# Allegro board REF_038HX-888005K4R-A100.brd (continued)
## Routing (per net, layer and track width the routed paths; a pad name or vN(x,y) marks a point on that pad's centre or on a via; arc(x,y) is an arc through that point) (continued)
D11610: length 268.7
  TOP w0.203: v2(100.55,223.11) 100.84,222.81 107.29,222.81 109.67,220.43 SITE1.140
  L03_SIGNAL w0.135: 113.5,288.23 113.5,291.58 116.74,294.82 116.74,308.89 135.13,327.28 135.13,361.68 155.3,381.84 174.7,381.84 178.67,385.81 178.67,389.22
  L03_SIGNAL w0.145: 178.67,389.22 D116.10 ; 113.5,288.23 113.77,287.96 v2(114.23,287.96)
  L22_SIGNAL w0.135: 100.18,222.74 99.21,222.74 99.08,222.88 99.08,223.11 98.94,223.25 98.67,223.25 98.54,223.11 98.54,222.88 98.4,222.74 98.14,222.74 98,222.88 98,223.11 97.87,223.25 97.6,223.25 97.46,223.11 97.46,222.88 97.33,222.74 89.36,222.74 81.7,230.4 81.7,274.98 83.63,276.91 103.31,276.91 104.63,278.23 104.63,284.74 105.97,286.08 112.79,286.08 113.5,286.79 113.5,287.69
  L22_SIGNAL w0.145: 113.5,287.69 113.77,287.96 v2(114.23,287.96) ; 100.18,222.74 v2(100.55,223.11)
D11611: length 268.7
  TOP w0.203: v2(97.25,224.28) 97.55,224.57 107.72,224.57 111.06,221.23 SITE1.138
  L05_SIGNAL w0.135: 113.09,281.99 113.09,281.09 112.83,280.82 112.14,280.82 110.83,282.13 110.83,305.69 132.32,327.18 132.32,378.45 155.49,401.62 175.76,401.62 181.27,396.11 181.27,395.14
  L05_SIGNAL w0.145: 113.09,281.99 112.83,282.26 v2(112.37,282.26) ; D116.11 177.53,393.7 177.4,393.84 177.4,394.51 177.65,394.76 180.89,394.76 181.27,395.14
  L20_SIGNAL w0.135: 96.88,224.64 92.4,224.64 91.6,225.44 91.6,234.12 98.2,240.72 98.2,265.76 113.09,280.66 113.09,281.99
  L20_SIGNAL w0.145: v2(97.25,224.28) 96.88,224.64 ; v2(112.37,282.26) 112.83,282.26 113.09,281.99
D11612: length 268.7
  TOP w0.203: SITE1.141 109.29,220.03 107.06,222.26 100.84,222.26 v2(100.55,221.97)
  L03_SIGNAL w0.135: 178.26,389.21 178.26,385.98 174.53,382.25 155.13,382.25 134.73,361.85 134.73,327.45 116.34,309.06 116.34,294.99 113.1,291.75 113.1,288.23
  L03_SIGNAL w0.145: v2(112.37,287.96) 112.83,287.96 113.1,288.23 ; D116.12 176.64,390.05 177.42,390.05 178.26,389.21
  L22_SIGNAL w0.135: 100.18,222.33 89.19,222.33 81.29,230.23 81.29,275.15 83.46,277.32 103.14,277.32 104.22,278.4 104.22,284.91 105.8,286.48 112.62,286.48 113.1,286.96 113.1,287.69
  L22_SIGNAL w0.145: v2(112.37,287.96) 112.83,287.96 113.1,287.69 ; 100.18,222.33 v2(100.55,221.97)
D11613: length 268.7
  TOP w0.203: SITE1.135 112.51,222.43 107.88,227.05 100.84,227.05 v2(100.55,227.35)
  L05_SIGNAL w0.135: 171.04,395.65 171.04,397.71 169.54,399.21 156.48,399.21 134.73,377.46 134.73,327.45 116.81,309.54 116.81,271.48 115.3,269.96 113.95,269.96 113.5,270.41 113.5,271.18
  L05_SIGNAL w0.145: 113.5,271.18 113.77,271.45 v2(114.23,271.45) ; D116.13 171.04,395.65
  L22_SIGNAL w0.135: 113.5,271.18 113.5,270.01 111.59,268.1 90.92,268.1 89.79,266.97 89.79,259.63 84.26,254.11 84.26,234.82 92.1,226.98 97.38,226.98 97.52,227.12 97.52,227.35 97.65,227.49 97.92,227.49 98.06,227.35 98.06,227.12 98.19,226.98 98.46,226.98 98.59,227.12 98.59,227.35 98.73,227.49 99,227.49 99.13,227.35 99.13,227.12 99.27,226.98 100.18,226.98
  L22_SIGNAL w0.145: 100.18,226.98 v2(100.55,227.35) ; v2(114.23,271.45) 113.77,271.45 113.5,271.18
D11614: length 268.7
  TOP w0.203: SITE1.142 108.52,219.63 107.27,220.88 97.55,220.88 v2(97.25,221.18)
  L03_SIGNAL w0.135: 113.5,299.04 113.5,308.36 132.32,327.18 132.32,362.85 154.13,384.65 165.43,384.65 168.47,387.7 168.47,389.18
  L03_SIGNAL w0.145: 113.5,299.04 113.77,298.77 v2(114.23,298.77) ; 168.47,389.18 D116.14
  L20_SIGNAL w0.135: 113.5,298.5 113.5,296.46 104.69,287.65 104.69,277.99 94.38,267.68 90.97,267.68 89.96,266.68 89.96,253.86 87.9,251.8 87.9,208.08 88.41,207.57 91.12,207.57 91.86,208.31 91.86,220.04 92.64,220.81 93.66,220.81 93.79,220.95 93.79,221.18 93.93,221.32 94.2,221.32 94.33,221.18 94.33,220.95 94.47,220.81 94.74,220.81 94.87,220.95 94.87,221.18 95.01,221.32 95.28,221.32 95.41,221.18 95.41,220.95 95.54,220.81 96.88,220.81
  L20_SIGNAL w0.145: 113.5,298.5 113.77,298.77 v2(114.23,298.77) ; v2(97.25,221.18) 96.88,220.81
D11615: length 268.7
  TOP w0.203: v2(100.55,226.21) 100.84,226.5 107.66,226.5 112.13,222.03 SITE1.136
  L05_SIGNAL w0.135: 170.63,395.64 170.63,397.54 169.37,398.8 156.65,398.8 135.13,377.29 135.13,327.28 117.22,309.37 117.22,271.31 115.47,269.55 113.78,269.55 113.1,270.24 113.1,271.18
  L05_SIGNAL w0.145: D116.15 169.24,395.03 170.03,395.03 170.63,395.64 ; 113.1,271.18 112.83,271.45 v2(112.37,271.45)
  L22_SIGNAL w0.135: 113.1,271.18 113.1,270.18 111.42,268.51 90.75,268.51 89.38,267.14 89.38,259.8 83.85,254.28 83.85,234.65 91.93,226.57 100.18,226.57
  L22_SIGNAL w0.145: 113.1,271.18 112.83,271.45 v2(112.37,271.45) ; 100.18,226.57 v2(100.55,226.21)
D11616: length 268.7
  TOP w0.203: v2(97.25,220.04) 97.55,220.33 107.04,220.33 108.15,219.23 SITE1.143
  L03_SIGNAL w0.135: 113.09,299.04 113.09,308.53 131.91,327.35 131.91,363.02 153.96,385.06 165.26,385.06 168.06,387.87 168.06,389.29
  L03_SIGNAL w0.145: D116.16 166.55,389.98 167.37,389.98 168.06,389.29 ; v2(112.37,298.77) 112.83,298.77 113.09,299.04
  L20_SIGNAL w0.135: 113.09,298.5 113.09,296.63 104.28,287.82 104.28,278.16 94.21,268.09 90.8,268.09 89.55,266.85 89.55,254.03 87.49,251.97 87.49,207.91 88.24,207.16 91.28,207.16 92.27,208.14 92.27,219.87 92.81,220.4 96.88,220.4
  L20_SIGNAL w0.145: v2(112.37,298.77) 112.83,298.77 113.09,298.5 ; v2(97.25,220.04) 96.88,220.4
D11701: length 198.5
  TOP w0.231: v1(125.12,201.03) 124.92,201.23 SITE1.19
  L03_SIGNAL w0.145: D117.01 14.24,97.79 14.24,101.6 18.68,106.05 35.19,106.05 58.04,128.89 58.04,172.69 S1_RST_N.1
  L22_SIGNAL w0.145: v1(125.12,201.03) 122.62,198.53 122.62,187.2 115.75,180.34 69.71,180.34 67.75,182.3 64.46,182.3 63.75,181.59 63.75,180.39 K10.3
  BOTTOM w0.231: S1_RST_N.1 60.35,175 62.86,175 63.76,175.9 63.76,177.15 K10.3
D11702: length 203.7
  TOP w0.203: v2(72.6,207.71) 73.26,208.36 76.27,208.36 80.1,204.53 85.52,204.53 89.34,208.36 108.81,208.36 108.88,208.43 SITE1.170
  L05_SIGNAL w0.135: 20.68,100.95 20.68,168.27 25.65,173.24 25.65,199.45 32.35,206.15 73.13,206.15 73.52,206.54 73.52,208.16 73.25,208.43 72.87,208.43 72.6,208.16 v2(72.6,207.71)
  L05_SIGNAL w0.145: 20.68,100.95 19.9,100.17 19.16,100.17 D117.02
D11703: length 274.1
  L03_SIGNAL w0.145: D117.03 16.78,92.71 14.39,92.71 13.6,93.5 13.6,102.23 21.36,109.99 21.36,169.62 26.26,174.52 26.26,192.25 39.82,205.8 75.04,205.8 85.84,216.6 97.63,216.6 102.92,221.9 108.67,221.9 117.11,230.33 136.49,230.33 146.76,220.06 149.73,220.06 151.51,218.27 166.14,218.27 v1(166.52,218.66)
D11704: length 203.7
  TOP w0.203: v2(72.6,209.57) 73.26,208.91 76.49,208.91 80.32,205.08 85.29,205.08 89.11,208.9 108.81,208.9 108.88,208.83 SITE1.169
  L05_SIGNAL w0.135: v2(72.6,209.57) 72.6,209.11 72.87,208.84 73.42,208.84 73.93,208.33 73.93,206.38 73.29,205.74 32.52,205.74 26.06,199.29 26.06,173.07 21.09,168.1 21.09,101.1
  L05_SIGNAL w0.145: D117.04 21.09,101.1
D11705: length 263.8
  TOP w0.231: SITE1.51 141.71,208.43 v1(142.71,207.43)
  L03_SIGNAL w0.145: D117.05 21.22,92.07 14.13,92.07 12.97,93.24 12.97,102.87 20.68,110.58 20.68,159.68 17.46,162.91 17.46,174.59 S1_I2C.2
  L22_SIGNAL w0.145: J5.2 39.82,175.81 K28.6 41.26,176.57 44.69,176.57 53.27,185.14 92.07,185.14 94.31,187.38 115.35,187.38 117.9,189.93 117.9,201.11 120.87,204.09 134.65,204.09 138.73,208.17 141.98,208.17 v1(142.71,207.43)
  BOTTOM w0.231: K28.6 41.44,174.18 41.44,171.93 40.54,171.03 21.02,171.03 S1_I2C.2
D11706: length 203.7
  TOP w0.203: v2(83.41,207.71) 84.07,208.36 84.9,208.36 86.88,210.35 108.34,210.35 109.46,209.23 SITE1.168
  L05_SIGNAL w0.135: 30.93,101.05 30.93,106.08 26.31,110.7 26.31,168.3 30.72,172.72 30.72,198.95 34.34,202.56 77.16,202.56 79.47,204.87 86.33,204.87 86.82,205.36 86.82,207.99 86.38,208.43 83.68,208.43 83.41,208.16 v2(83.41,207.71)
  L05_SIGNAL w0.145: D117.06 29.32,100.17 30.04,100.17 30.93,101.05
D11707: length 291.3
  TOP w0.231: v1(166.52,220.56) 166.54,220.58 RT9.1
  L03_SIGNAL w0.145: v1(166.52,220.56) 166.46,220.62 147.7,220.62 137.33,230.99 116.26,230.99 108.23,222.96 102.48,222.96 97.48,217.96 85.63,217.96 76.31,208.65 40.1,208.65 18.49,187.04 18.49,178.01 16.16,175.68 16.16,161.1 17.55,159.72 17.55,108.72 12.33,103.5 12.33,92.97 13.87,91.44 25.67,91.44 D117.07
D11708: length 203.7
  TOP w0.203: v2(83.41,209.57) 84.07,208.91 84.67,208.91 86.66,210.9 108.57,210.9 109.83,209.63 SITE1.167
  L05_SIGNAL w0.135: 31.34,101.01 31.34,106.25 26.71,110.87 26.71,168.13 31.13,172.55 31.13,198.78 34.51,202.16 77.33,202.16 79.63,204.46 86.5,204.46 87.23,205.19 87.23,208.16 86.55,208.84 83.68,208.84 83.41,209.11 v2(83.41,209.57)
  L05_SIGNAL w0.145: D117.08 31.34,101.01
D11709: length 266.6
  TOP w0.231: SITE1.50 140.72,208.03 v1(141.32,207.43)
  L03_SIGNAL w0.145: D117.09 30.11,90.8 13.6,90.8 11.7,92.71 11.7,104.14 15.51,107.95 15.51,154.86 15.3,155.07 15.3,169.57 14.75,170.12 S1_I2C.1
  L22_SIGNAL w0.145: v1(141.32,207.43) 140.46,206.57 139.52,206.57 135.34,202.39 123.54,202.39 120.52,199.38 120.52,188.64 116.56,184.68 95.39,184.68 93.72,183.02 57.95,183.02 51.77,176.85 48.51,176.85 J4.2 43.7,175.81 K28.3
  BOTTOM w0.231: K28.3 42.18,174.29 42.18,171.62 40.85,170.28 19.22,170.28 S1_I2C.1
D11710: length 203.7
  TOP w0.203: v2(72.6,192.47) 73.26,193.12 76.05,193.12 81.28,187.9 92.97,187.9 95.26,190.19 95.26,199.96 98.07,202.78 110.34,202.78 113.59,206.03 SITE1.176
  L05_SIGNAL w0.135: v2(72.6,192.47) 72.6,192.92 72.87,193.19 73.63,193.19 74.06,192.76 74.06,191.51 73.41,190.86 65.66,190.86 60.99,195.53 48.91,195.53 46.65,193.27 46.65,185.33 44.61,183.29 35.36,183.29 33.42,181.35 33.42,169.7 30.91,167.2 30.91,114.21 41,104.12 41,101.06
  L05_SIGNAL w0.145: D117.10 39.87,100.56 40.5,100.56 41,101.06
D11711: length 181
  L03_SIGNAL w0.145: D117.11 45.35,92.07 56.52,92.07 57.42,92.97 57.42,113.16 67.08,122.83 67.08,159.52 92.11,184.55 92.11,202.47 96.71,207.08 96.71,210.63 102.72,216.63 102.72,219.29 104.38,220.96 116.24,220.96 v1(118.36,218.83)
D11712: length 203.7
  TOP w0.203: SITE1.175 113.21,206.43 110.11,203.33 97.85,203.33 94.71,200.19 94.71,190.42 92.74,188.44 81.51,188.44 76.28,193.67 73.26,193.67 v2(72.6,194.33)
  L05_SIGNAL w0.135: v2(72.6,194.33) 72.6,193.87 72.87,193.6 73.8,193.6 74.47,192.93 74.47,191.34 73.58,190.45 65.49,190.45 60.82,195.12 49.08,195.12 47.06,193.1 47.06,185.16 44.78,182.88 35.53,182.88 33.83,181.18 33.83,169.53 31.32,167.03 31.32,114.38 41.41,104.29 41.41,101.1
  L05_SIGNAL w0.145: D117.12 41.41,101.1
D11713: length 203.7
  TOP w0.203: SITE1.174 111.8,206.83 109.67,204.7 95.22,204.7 92.32,201.8 92.32,194.5 90.94,193.12 88.5,193.12 v2(87.84,192.47)
  L05_SIGNAL w0.135: v2(87.84,192.47) 87.84,192.92 87.58,193.18 87.39,193.18 87.05,192.84 87.05,191.78 87.56,191.27 87.56,189.52 80.69,182.66 64.87,182.66 61.3,186.23 57.38,186.23 56.18,185.03 56.18,183.86 54.04,181.73 54.04,168.5 52.34,166.79 44.41,166.79 42.23,164.61 42.23,119.8 59.32,102.7 59.32,94.44 56.87,91.99 48.91,91.99 48.09,92.81 48.09,94.42
  L05_SIGNAL w0.145: D117.13 48.09,94.42
D11714: length 203.7
  TOP w0.203: SITE1.172 110.67,207.63 109.56,206.52 92.24,206.52 85.64,199.92 85.64,193.89 84.87,193.12 84.07,193.12 v2(83.41,192.47)
  L05_SIGNAL w0.135: v2(83.41,192.47) 83.41,192.92 83.68,193.19 83.96,193.19 84.23,192.92 84.23,189.65 83.14,188.56 77.44,188.56 76.34,187.47 65.4,187.47 60.06,192.81 52.45,192.81 51.2,191.56 51.2,183.3 50.33,182.43 47.58,182.43 45.97,180.82 45.97,178.59 46.91,177.65 50.39,177.65 51.2,176.84 51.2,172.76 49.39,170.95 38.42,170.95 35.89,168.42 35.89,118.44 51.17,103.15 51.17,101.09
  L05_SIGNAL w0.145: 51.17,101.09 50.75,100.66 50.13,100.66 D117.14
D11715: length 203.7
  TOP w0.203: SITE1.173 111.43,207.23 109.44,205.25 95,205.25 91.77,202.02 91.77,194.73 90.71,193.67 88.5,193.67 v2(87.84,194.33)
  L05_SIGNAL w0.135: v2(87.84,194.33) 87.84,193.87 87.57,193.6 87.23,193.6 86.64,193.01 86.64,191.61 87.15,191.1 87.15,189.69 80.52,183.07 65.04,183.07 61.46,186.64 57.21,186.64 55.77,185.2 55.77,184.03 53.63,181.9 53.63,168.67 52.17,167.2 44.24,167.2 41.82,164.78 41.82,119.63 58.92,102.53 58.92,94.61 56.7,92.39 49.08,92.39 48.5,92.98 48.5,94.41
  L05_SIGNAL w0.145: 48.5,94.41 49.11,95.02 50.02,95.02 51.07,96.06 D117.15
D11716: length 203.7
  TOP w0.203: SITE1.171 110.3,208.03 109.33,207.07 92.01,207.07 85.09,200.15 85.09,194.12 84.64,193.67 84.07,193.67 v2(83.41,194.33)
  L05_SIGNAL w0.135: 51.58,101.09 51.58,103.32 36.3,118.61 36.3,168.25 38.59,170.54 49.56,170.54 51.61,172.59 51.61,177.01 50.56,178.06 47.08,178.06 46.38,178.76 46.38,180.65 47.75,182.02 50.5,182.02 51.61,183.13 51.61,191.39 52.62,192.4 59.89,192.4 65.23,187.06 76.51,187.06 77.61,188.15 83.31,188.15 84.64,189.48 84.64,193.09 84.13,193.6 83.68,193.6 83.41,193.87 v2(83.41,194.33)
  L05_SIGNAL w0.145: D117.16 51.58,101.09
D11801: length 168.3
  L05_SIGNAL w0.135: 121.87,129.09 121.87,128.47 120.21,126.81 106.65,126.81 85.42,105.58 85.42,68.94 79.05,62.58 19.9,62.58 17.36,65.12 17.36,74.35
  L05_SIGNAL w0.145: 121.87,129.09 122.14,129.36 v1(123.26,129.36) ; 17.36,74.35 D118.01
D11802: length 203.7
  TOP w0.203: v2(98.65,192.47) 99.31,193.12 99.97,193.12 100.49,193.65 100.49,197.69 103.61,200.8 117.55,200.8 118.12,201.37 SITE1.2
  L05_SIGNAL w0.135: 20.31,81 20.31,83.24 27.47,90.4 58.43,90.4 61.9,93.86 61.9,105.28 60.65,106.53 60.65,151.22 62.27,152.85 62.27,167.72 70.95,176.4 79.15,176.4 94.01,191.25 98.94,191.25 99.56,191.87 99.56,192.94 99.3,193.19 98.92,193.19 98.65,192.92 v2(98.65,192.47)
  L05_SIGNAL w0.145: D118.02 20.31,81
D11803: length 168.3
  L05_SIGNAL w0.135: 17.77,74.35 17.77,65.29 20.07,62.99 78.88,62.99 85.01,69.11 85.01,105.75 106.48,127.22 120.04,127.22 121.46,128.63 121.46,129.09
  L05_SIGNAL w0.145: 17.77,74.35 18.25,74.82 19.87,74.82 20.59,75.54 D118.03 ; 121.46,129.09 121.19,129.36 v1(120.06,129.36)
D11804: length 203.7
  TOP w0.203: v2(98.65,194.33) 99.31,193.67 99.74,193.67 99.94,193.87 99.94,197.91 103.38,201.35 117.33,201.35 117.72,201.74 SITE1.1
  L05_SIGNAL w0.135: 20.71,80.98 20.71,83.07 27.63,89.99 58.6,89.99 62.31,93.7 62.31,105.45 61.06,106.7 61.06,151.05 62.68,152.68 62.68,167.55 71.12,175.99 79.32,175.99 94.18,190.85 99.11,190.85 99.96,191.7 99.96,193.11 99.47,193.6 98.92,193.6 98.65,193.87 v2(98.65,194.33)
  L05_SIGNAL w0.145: D118.04 22.95,78.74 20.71,80.98
D11805: length 213.5
  TOP w0.203: v2(111.9,160.49) 111.24,161.15 111.24,162.36 114.99,166.11 114.99,174.85 125.29,185.15 125.29,191.85 123.72,193.42 SITE1.16
  L05_SIGNAL w0.135: v2(111.9,160.49) 111.44,160.49 111.17,160.23 111.17,157.7 112.66,156.21 112.66,137.57 81.82,106.73 81.82,80.24 67.45,65.88 29.97,65.88 27.59,68.26 27.59,74.28
  L05_SIGNAL w0.145: D118.05 27.59,74.28
D11806: length 213.5
  TOP w0.203: SITE1.6 119.72,200.3 115.28,195.87 115.28,192.72 110.05,187.49 96.73,187.49 96,186.76 96,186.18 v2(96.66,185.53)
  L05_SIGNAL w0.135: 30.98,80.79 30.98,86.78 32.55,88.35 60.23,88.35 64.9,93.02 64.9,123.4 68.17,126.67 68.17,165.67 75.04,172.55 82,172.55 91.57,182.12 103.36,182.12 103.95,182.71 103.95,186.68 103.27,187.37 96.43,187.37 95.93,186.87 95.93,185.8 96.2,185.53 v2(96.66,185.53)
  L05_SIGNAL w0.145: D118.06 28.21,79.82 28.58,80.2 30.39,80.2 30.98,80.79
D11807: length 213.5
  TOP w0.203: v2(110.04,160.49) 110.69,161.15 110.69,162.59 114.44,166.34 114.44,175.08 124.74,185.37 124.74,191.62 123.32,193.04 SITE1.15
  L05_SIGNAL w0.135: v2(110.04,160.49) 110.49,160.49 110.76,160.23 110.76,157.53 112.26,156.04 112.26,137.74 81.41,106.9 81.41,80.41 67.29,66.29 30.14,66.29 28,68.43 28,74.28
  L05_SIGNAL w0.145: 28,74.28 28.55,74.84 30.38,74.84 30.75,75.21 D118.07
D11808: length 213.5
  TOP w0.203: SITE1.5 119.32,200.68 114.73,196.09 114.73,192.95 109.82,188.04 96.5,188.04 95.45,186.99 95.45,186.18 v2(94.8,185.53)
  L05_SIGNAL w0.135: 31.39,80.75 31.39,86.61 32.72,87.94 60.4,87.94 65.31,92.86 65.31,123.23 68.58,126.5 68.58,165.5 75.21,172.14 82.17,172.14 91.74,181.71 103.53,181.71 104.36,182.54 104.36,186.85 103.44,187.78 96.26,187.78 95.52,187.03 95.52,185.8 95.25,185.53 v2(94.8,185.53)
  L05_SIGNAL w0.145: 31.39,80.75 33.29,78.85 D118.08
D11809: length 213.5
  TOP w0.203: SITE1.14 122.92,186.63 111.24,174.95 111.24,171.96 v2(111.9,171.3)
  L05_SIGNAL w0.135: 37.62,74.41 37.62,70.6 39.51,68.72 65.11,68.72 78.54,82.14 78.54,108.68 104.67,134.82 104.67,147.89 100.44,152.13 100.44,161.53 100.93,162.02 102.38,162.02 103.02,161.37 103.02,156.33 104.1,155.26 107.22,155.26 108.22,156.26 108.22,163.83 111.17,166.78 111.17,171.03 111.44,171.3 v2(111.9,171.3)
  L05_SIGNAL w0.145: D118.09 37.62,74.41
D11810: length 213.5
  TOP w0.203: v2(96.66,174.72) 96,175.37 96,178.38 102.13,184.51 109.83,184.51 117.15,191.83 117.15,194.75 120.52,198.12 SITE1.8
  L05_SIGNAL w0.135: 40.15,80.53 40.15,84.58 41.69,86.11 61.58,86.11 67.71,92.24 67.71,120.64 76.25,129.18 76.25,140.16 77.45,141.35 77.45,150.8 76.28,151.97 74.25,151.97 72.7,153.52 72.7,165.96 73.79,167.06 77.09,167.06 78.21,165.94 78.21,155.74 78.75,155.2 81.26,155.2 81.86,155.79 81.86,167.93 89.98,176.05 95.42,176.05 95.93,175.54 95.93,174.99 96.2,174.72 v2(96.66,174.72)
  L05_SIGNAL w0.145: D118.10 40.15,80.53
D11811: length 213.5
  TOP w0.203: v2(110.04,171.3) 110.69,171.96 110.69,175.18 122.52,187 SITE1.13
  L05_SIGNAL w0.135: v2(110.04,171.3) 110.49,171.3 110.76,171.03 110.76,166.95 107.81,164 107.81,156.42 107.05,155.67 104.26,155.67 103.43,156.5 103.43,161.54 102.55,162.43 100.76,162.43 100.03,161.7 100.03,151.96 104.26,147.72 104.26,134.99 78.13,108.85 78.13,82.31 64.94,69.13 39.68,69.13 38.03,70.77 38.03,74.45
  L05_SIGNAL w0.145: 38.03,74.45 38.45,74.87 39.9,74.87 40.91,75.88 D118.11
D11812: length 213.5
  TOP w0.203: SITE1.7 120.12,198.5 116.6,194.98 116.6,192.05 109.6,185.05 101.9,185.05 95.45,178.61 95.45,175.37 v2(94.8,174.72)
  L05_SIGNAL w0.135: 40.56,80.58 40.56,84.41 41.85,85.7 61.75,85.7 68.12,92.07 68.12,120.47 76.66,129.01 76.66,139.99 77.86,141.18 77.86,150.97 76.45,152.38 74.42,152.38 73.11,153.69 73.11,165.79 73.96,166.65 76.92,166.65 77.8,165.77 77.8,155.57 78.58,154.79 81.43,154.79 82.27,155.62 82.27,167.76 90.14,175.64 95.25,175.64 95.52,175.37 95.52,174.99 95.25,174.72 v2(94.8,174.72)
  L05_SIGNAL w0.145: 40.56,80.58 40.98,80.16 42.41,80.16 43.45,79.12 D118.12
D11813: length 213.5
  TOP w0.203: SITE1.12 122.12,194 120.89,192.77 120.89,188.73 96,163.84 96,161.15 v2(96.66,160.49)
  L05_SIGNAL w0.135: 47.68,74.51 47.68,72.27 48.62,71.34 63.5,71.34 74.34,82.18 74.34,108.3 89.3,123.26 89.3,124.23 88.17,125.36 86.98,125.36 75.89,114.26 75.01,114.26 74.38,114.89 74.38,116 89.45,131.08 89.45,148.3 95.93,154.78 95.93,160.23 96.2,160.49 v2(96.66,160.49)
  L05_SIGNAL w0.145: D118.13 47.68,74.51
D11814: length 213.5
  TOP w0.203: SITE1.10 121.32,196.22 118.86,193.76 118.86,190.36 110.18,181.68 107.09,181.68 98.24,172.83 96.36,172.83 96,172.47 96,171.96 v2(96.66,171.3)
  L05_SIGNAL w0.135: 51.37,80.57 51.37,82.94 51.9,83.48 67.54,83.48 70.77,86.7 70.77,117.38 86.8,133.42 86.8,162.44 87.95,163.59 96.82,163.59 97.44,164.21 97.44,166.1 97.17,166.37 88.82,166.37 88,167.19 88,169.87 88.96,170.82 91.21,170.82 92.37,169.67 101.81,169.67 105.17,173.02 105.17,173.92 104.37,174.72 103.14,174.72 101.08,172.66 96.31,172.66 95.93,172.28 95.93,171.57 96.2,171.3 v2(96.66,171.3)
  L05_SIGNAL w0.145: 51.37,80.57 50.88,80.09 49.17,80.09 48.53,79.45 D118.14
D11815: length 213.5
  TOP w0.203: v2(94.8,160.49) 95.45,161.15 95.45,164.07 120.34,188.96 120.34,193 121.72,194.38 SITE1.11
  L05_SIGNAL w0.135: 48.09,74.52 48.09,72.44 48.79,71.75 63.33,71.75 73.93,82.35 73.93,108.47 88.89,123.43 88.89,124.06 88,124.95 87.15,124.95 76.06,113.85 74.84,113.85 73.97,114.73 73.97,116.17 89.04,131.25 89.04,148.47 95.52,154.95 95.52,160.23 95.25,160.49 v2(94.8,160.49)
  L05_SIGNAL w0.145: D118.15 49.87,75 48.57,75 48.09,74.52
D11816: length 213.5
  TOP w0.203: SITE1.9 120.92,196.6 118.31,193.99 118.31,190.59 109.95,182.23 106.86,182.23 98.01,173.38 96.14,173.38 95.45,172.69 95.45,171.96 v2(94.8,171.3)
  L05_SIGNAL w0.135: v2(94.8,171.3) 95.25,171.3 95.52,171.57 95.52,172.45 96.14,173.07 100.91,173.07 102.97,175.13 104.54,175.13 105.57,174.09 105.57,172.85 101.98,169.26 92.2,169.26 91.04,170.41 89.13,170.41 88.41,169.7 88.41,167.36 88.98,166.78 97.34,166.78 97.85,166.27 97.85,164.04 96.98,163.18 88.12,163.18 87.21,162.27 87.21,133.25 71.17,117.21 71.17,86.54 67.71,83.07 52.07,83.07 51.78,82.77 51.78,80.57
  L05_SIGNAL w0.145: D118.16 51.78,80.57
D11901: length 238.4
  TOP w0.231: v1(118.44,209.83) 117.84,210.43 SITE1.165
  L03_SIGNAL w0.145: v1(118.44,209.83) 117.5,208.89 117.5,205.26 117.29,205.04 117.29,200.68 117.58,200.39 117.58,189.7 116.11,188.23 116.11,179.59 108.82,172.31 108.82,167.96 103.85,163 103.85,140.45 67.58,104.17 67.58,68.64 63.13,64.2 63.13,50.86 59.9,47.62 23.76,47.62 D119.01
D11902: length 282.8
  TOP w0.231: SITE1.149 117.72,216.83 v1(118.32,217.43)
  L03_SIGNAL w0.145: D119.02 19.21,59.58 19.21,61.89 18.77,62.33 14.71,62.33 13.81,61.43 13.81,55.72 12.99,54.9 4.12,54.9 3.33,55.69 3.33,71.44 4.28,72.39 56.85,72.39 58.05,73.6 58.05,112.9 67.82,122.67 67.82,158.99 92.74,183.91 92.74,202.21 97.35,206.82 97.35,210.36 103.35,216.37 103.35,219.03 104.65,220.32 111.43,220.32 113.64,218.12 117.63,218.12 v1(118.32,217.43)
D11903: length 229.9
  TOP w0.231: SITE1.166 116.85,210.03 v1(117.05,209.83)
  L03_SIGNAL w0.145: D119.03 28.21,48.26 59.63,48.26 62.5,51.13 62.5,64.46 66.94,68.91 66.94,105.5 94.11,132.66 94.11,133.3 103.23,142.42 103.23,163.75 108.11,168.63 108.11,172.44 115.47,179.8 115.47,190.24 116.75,191.52 116.75,205.25 116.98,205.47 116.98,209.63 117.05,209.7 v1(117.05,209.83)
D11904: length 271.1
  TOP w0.231: SITE1.153 110.93,215.23 v1(109.92,216.23)
  L03_SIGNAL w0.145: v1(109.92,216.23) 108.47,216.23 108.26,216.01 103.9,216.01 97.98,210.1 97.98,206.55 93.38,201.95 93.38,183.28 68.71,158.61 68.71,122.66 58.69,112.64 58.69,73.33 57.11,71.75 5.47,71.75 4.45,70.74 4.45,56.7 5.12,56.03 11.63,56.03 12.31,56.72 12.31,62.38 13.33,63.39 20.82,63.39 21.83,62.38 21.83,59.72 D119.04
D11905: length 224.2
  L03_SIGNAL w0.145: v1(118.36,211.63) 117.52,210.79 116.69,210.79 116.45,210.55 116.45,205.69 116.11,205.35 116.11,191.78 114.84,190.5 114.84,180.05 107.1,172.32 107.1,169.18 101.49,163.57 101.49,160.06 89.54,148.11 89.54,128.99 66.31,105.76 66.31,69.17 61.86,64.72 61.86,51.39 59.37,48.89 32.65,48.89 D119.05
D11906: length 282.8
  TOP w0.231: v1(111.32,216.23) 111.92,215.63 SITE1.152
  L03_SIGNAL w0.145: D119.06 31.55,61.76 31.55,64.71 30.84,65.42 12.28,65.42 11.32,64.46 11.32,57.47 10.88,57.03 6.19,57.03 5.45,57.77 5.45,70.11 6.46,71.12 57.37,71.12 59.32,73.07 59.32,112.37 69.55,122.6 69.55,155.64 94.2,180.29 94.2,199.23 97.01,202.04 97.01,204.32 98.02,205.33 101.27,205.33 103.03,207.09 103.03,213.14 104.12,214.23 107.76,214.23 108.96,215.42 110.51,215.42 v1(111.32,216.23)
D11907: length 223.1
  TOP w0.231: v1(116.92,213.43) 116.72,213.23 SITE1.158
  L03_SIGNAL w0.145: D119.07 37.1,49.53 59.11,49.53 61.23,51.65 61.23,64.99 65.67,69.43 65.67,106.22 88.73,129.28 88.73,148.93 100.2,160.39 100.2,167.73 114.2,181.73 114.2,202.6 112.83,203.97 112.83,207.52 113.12,207.8 113.12,209.69 113.69,210.26 115.29,210.26 116.61,211.58 116.61,213.12 v1(116.92,213.43)
D11908: length 204.2
  TOP w0.231: SITE1.157 110.93,213.63 v1(109.92,214.63)
  L03_SIGNAL w0.145: D119.08 45.35,70.48 57.64,70.48 59.96,72.81 59.96,110.08 76.19,126.3 76.19,161.01 95.37,180.19 95.37,199.5 97.65,201.78 97.65,204.06 98.29,204.7 104.11,204.7 104.58,205.17 104.58,209.51 106.57,211.5 106.57,211.86 109.35,214.63 v1(109.92,214.63)
D11909: length 217.4
  TOP w0.231: v1(116.92,215.03) 116.72,214.83 SITE1.154
  L03_SIGNAL w0.145: D119.09 41.54,50.16 58.84,50.16 60.59,51.92 60.59,65.25 65.04,69.7 65.04,106.48 88.1,129.54 88.1,149.85 98.23,159.98 98.23,167.4 112.03,181.2 112.03,189.34 112.57,189.88 112.57,199.45 111.41,200.61 111.41,207.05 112.46,208.11 112.46,209.78 113.43,210.74 113.43,211.54 v1(116.92,215.03)
D11910: length 196.7
  TOP w0.231: SITE1.156 111.92,214.03 v1(111.32,214.63)
  L03_SIGNAL w0.145: v1(111.32,214.63) 110.54,213.85 109.53,213.85 107.39,211.71 107.39,210.18 105.42,208.2 105.42,203.78 105.03,203.4 102.96,203.4 96.01,196.45 96.01,178.29 77.01,159.29 77.01,126.23 60.59,109.81 60.59,72.54 57.9,69.85 49.8,69.85 D119.10
D11911: length 282.8
  TOP w0.231: v1(112.72,216.23) 112.92,216.03 SITE1.151
  L03_SIGNAL w0.145: D119.11 42.01,54.78 42.01,52.35 43.41,50.95 48.92,50.95 49.86,51.88 49.86,56.32 50.61,57.08 57.16,57.08 59.32,59.25 59.32,65.78 63.77,70.22 63.77,107.01 84.21,127.45 84.21,150.17 93.79,159.75 93.79,160.74 92.96,161.57 91.54,161.57 85.17,155.2 84.51,155.2 84.21,155.5 84.21,156.47 101.29,173.55 101.29,187.62 101.63,187.96 102.92,187.96 103.25,187.63 103.25,177.28 103.55,176.98 104.75,176.98 105.08,177.3 105.08,187.85 105.41,188.19 106.63,188.19 106.85,187.98 106.85,181.63 107.31,181.16 108.35,181.16 108.79,181.6 108.79,189.16 108.31,189.65 102.89,189.65 101.3,191.23 101.29,191.23 101.29,196.8 104.03,199.54 108.9,199.54 110.26,200.9 110.26,207.89 111.1,208.73 111.1,210.27 113.44,212.61 113.44,215.51 v1(112.72,216.23)
D11912: length 191.2
  TOP w0.231: SITE1.161 110.93,212.03 v1(109.92,213.03)
  L03_SIGNAL w0.145: D119.12 54.24,69.22 58.16,69.22 61.23,72.28 61.23,108.06 77.74,124.57 77.74,157.1 90.44,169.8 90.44,171.45 97.23,178.24 97.23,196.76 103.23,202.76 105.67,202.76 106.18,203.28 106.18,208.06 108.16,210.04 108.16,211.26 v1(109.92,213.03)
D11913: length 192.3
  TOP w0.231: SITE1.155 112.92,214.43 v1(112.72,214.63)
  L03_SIGNAL w0.145: D119.13 47.32,57.21 49.4,57.21 49.92,57.73 49.92,59.04 62.5,71.61 62.5,107.53 81.17,126.21 81.17,151.66 82.08,152.57 82.08,157.59 95.52,171.03 95.52,172.5 100,176.98 100,197.54 103.23,200.77 107.55,200.77 107.7,200.92 107.7,207.67 109.67,209.65 109.67,210.58 112.02,212.92 112.02,213.93 v1(112.72,214.63)
D11914: length 186
  TOP w0.231: SITE1.160 111.92,212.43 v1(111.32,213.03)
  L03_SIGNAL w0.145: v1(111.32,213.03) 108.88,210.58 108.88,209.82 106.98,207.93 106.98,202.7 105.69,201.41 102.97,201.41 98.09,196.53 98.09,177.83 95.52,175.26 95.52,173.99 91.07,169.54 91.07,168.44 81.37,158.73 81.37,153 80.38,152.02 80.38,126.31 61.86,107.79 61.86,72.25 61.81,72.19 61.81,72.04 58.4,68.64 58.25,68.64 48.53,58.91 D119.14
D11915: length 189.1
  TOP w0.231: v1(112.72,211.03) 112.92,211.23 SITE1.163
  L03_SIGNAL w0.145: v1(112.72,211.03) 111.77,210.08 111.77,208.4 110.83,207.46 110.83,199.71 111.42,199.12 111.42,193.67 110.74,192.99 110.74,181.72 95.55,166.53 95.55,159.94 86.67,151.06 86.67,129.01 64.4,106.75 64.4,69.96 59.96,65.51 59.96,56.58 58.08,54.69 52.26,54.69 D119.15
D11916: length 184.5
  TOP w0.231: v1(112.72,213.03) 112.92,212.83 SITE1.159
  L03_SIGNAL w0.145: v1(112.72,213.03) 112.72,212.77 110.47,210.51 110.47,209.11 109.64,208.29 109.64,201.05 108.73,200.14 103.49,200.14 100.63,197.28 100.63,174.53 96.88,170.77 96.6,170.77 83.44,157.62 83.44,127.58 63.13,107.27 63.13,70.48 58.69,66.04 58.69,63.5 D119.16
D12001: length 297.1
  L03_SIGNAL w0.145: v1(129.97,207.69) 129.04,206.75 129.04,205.91 129.74,205.21 129.74,200.68 131.21,199.21 131.21,176.21 140.66,166.76 140.66,146.11 141.46,145.3 141.46,140.79 141.36,140.68 141.36,140.36 140.62,139.63 140.62,133.44 110.62,103.43 91.44,103.43 84.87,96.87 84.87,30.84 78.7,24.67 22.15,24.67 14.16,32.66 14.16,34.21 D120.01
D12002: length 231.1
  L03_SIGNAL w0.145: v1(118.77,207.69) 118.03,206.94 118.03,204.9 118.45,204.48 118.45,201.46 118.27,201.28 118.27,189.14 117.74,188.61 117.74,179.03 110.76,172.05 110.76,167.3 104.49,161.03 104.49,140.18 68.21,103.91 68.21,68.38 63.77,63.93 63.77,50.6 60.16,46.99 26.94,46.99 D120.02
D12003: length 289.8
  L03_SIGNAL w0.145: D120.03 19.31,34.28 19.31,32.43 26.38,25.35 78.15,25.35 84.19,31.39 84.19,97.15 91.16,104.11 110.34,104.11 139.96,133.74 139.96,166.47 130.51,175.92 130.51,198.92 128.59,200.84 128.59,205.47 128.34,205.72 128.34,206.92 v1(127.57,207.69)
D12004: length 234.9
  TOP w0.231: SITE1.164 118.84,210.83 v1(119.84,209.83)
  L03_SIGNAL w0.145: D120.04 31.38,46.35 60.42,46.35 64.4,50.34 64.4,63.67 68.85,68.12 68.85,103.64 105.12,139.92 105.12,160.49 112.61,167.98 112.61,172.84 118.38,178.6 118.38,188.35 118.92,188.89 118.92,201.19 118.98,201.25 118.98,204.69 118.92,204.75 118.92,204.75 118.56,205.12 118.56,205.65 120.23,207.32 120.23,209.44 v1(119.84,209.83)
D12005: length 219.9
  L03_SIGNAL w0.145: D120.05 35.11,26.12 77.78,26.12 83.45,31.8 83.45,97.58 91.36,105.48 102.31,105.48 137.54,140.71 137.54,157.13 K14.2
D12006: length 282.8
  TOP w0.231: v1(119.71,217.43) 118.71,216.43 SITE1.150
  L03_SIGNAL w0.145: D120.06 35.83,45.72 60.69,45.72 65.04,50.07 65.04,63.41 69.48,67.85 69.48,103.38 106.41,140.31 106.41,158.83 107.02,159.44 107.96,159.44 108.55,158.86 108.55,146.7 108.86,146.39 109.57,146.39 109.87,146.69 109.87,159.15 110.33,159.6 111.38,159.6 111.84,159.14 111.84,152.91 112.09,152.66 112.87,152.66 113.1,152.89 113.1,166.22 113.51,166.63 113.51,172.88 119.01,178.38 119.01,187.34 120.31,188.64 120.31,197.77 124.14,201.6 124.14,204.84 121.07,207.91 121.07,216.07 v1(119.71,217.43)
D12007: length 219.9
  L03_SIGNAL w0.145: K14.7 136.72,157.11 136.72,141.26 104.82,109.35 96.65,109.35 96.38,109.07 96.38,108.2 96.57,108.01 98.87,108.01 99.19,107.69 99.19,107.01 98.93,106.75 91.36,106.75 82.82,98.21 82.82,32.08 77.5,26.76 39.55,26.76 D120.07
D12008: length 236.5
  L03_SIGNAL w0.145: v1(122.16,222.59) 121.71,222.14 121.71,210.21 123.81,208.11 123.81,206.75 124.64,205.92 124.95,205.92 125.23,205.65 125.23,201.92 120.94,197.64 120.94,188.37 119.65,187.08 119.65,177.99 116.46,174.8 116.46,168.61 113.9,166.05 113.9,145.33 70.12,101.54 70.12,67.59 65.67,63.15 65.67,49.81 60.95,45.09 40.27,45.09 D120.08
D12009: length 219.9
  L03_SIGNAL w0.145: K15.2 129.46,157.18 129.46,138.71 121.96,131.21 121.96,128.61 106.97,113.62 98.02,113.62 97.63,113.23 97.63,112.37 97.91,112.09 104.98,112.09 105.2,111.86 105.2,110.95 105.06,110.8 94.14,110.8 82.18,98.85 82.18,32.34 77.24,27.39 44,27.39 D120.09
D12010: length 236.2
  TOP w0.231: v1(123.52,224.03) 123.32,224.23 SITE1.118
  L03_SIGNAL w0.145: D120.10 44.72,44.45 61.21,44.45 66.31,49.55 66.31,62.88 70.75,67.33 70.75,101.28 115.23,145.75 115.23,166.5 117.42,168.69 117.42,174.47 121.55,178.61 121.55,186.9 122.45,187.8 122.45,197.91 124.92,200.38 125.53,200.38 125.8,200.65 125.8,205.94 125.49,206.25 125.49,207.61 122.45,210.65 122.45,218.92 123.52,219.99 v1(123.52,224.03)
D12011: length 219.9
  L03_SIGNAL w0.145: K15.7 128.52,157.19 128.52,139.11 122.21,132.8 120.32,132.8 119.24,131.72 119.24,129.84 111.95,122.56 110.95,122.56 109.97,123.54 109.97,124.26 116.82,131.12 116.82,132.1 116.12,132.8 114.86,132.8 81.55,99.48 81.55,32.6 76.97,28.03 48.44,28.03 D120.11
D12012: length 233.9
  L03_SIGNAL w0.145: D120.12 44.68,36.87 57.69,36.87 68.57,47.76 68.57,61.3 73.21,65.94 73.21,98.42 118.63,143.85 118.63,162.79 118.78,162.93 119.99,162.93 122.08,165.03 122.08,175.17 124.43,177.52 124.43,180.21 128.35,184.14 128.35,199.39 127.62,200.13 127.62,201.09 127.11,201.6 127.11,205.82 126.78,206.15 126.78,207.23 123.09,210.91 123.09,218.32 126.12,221.35 v1(126.12,222.59)
D12013: length 195.4
  L03_SIGNAL w0.135: 121.87,158.04 121.87,142.55 78.15,98.84 78.15,51.05 66.24,39.14 66.24,37.4 66.99,36.65 68.06,36.65 73.15,41.74 74.81,41.74 75.9,40.65 75.9,39.44 67.03,30.56 49.66,30.56 47.95,32.28 47.95,33.6
  L03_SIGNAL w0.145: 121.87,158.04 122.14,158.31 K9.2 ; D120.13 47.95,33.6
D12014: length 201.2
  TOP w0.231: v1(125.12,199.63) 124.52,200.23 SITE1.18
  L03_SIGNAL w0.145: D120.14 54.24,43.81 61.48,43.81 66.94,49.28 66.94,62.62 71.39,67.06 71.39,101.01 117.02,146.64 117.02,165.81 118.18,166.97 118.18,174.16 122.19,178.17 122.19,186.64 123.09,187.54 123.09,197.6 v1(125.12,199.63)
D12015: length 195.4
  L03_SIGNAL w0.135: 48.36,33.6 48.36,32.45 49.83,30.97 66.86,30.97 75.5,39.61 75.5,40.48 74.64,41.33 73.32,41.33 68.23,36.24 66.82,36.24 65.83,37.23 65.83,39.31 77.74,51.22 77.74,99.01 121.46,142.72 121.46,158.04
  L03_SIGNAL w0.145: D120.15 51.07,34.53 50.7,34.16 48.91,34.16 48.36,33.6 ; 121.46,158.04 121.19,158.31 K9.7
D12016: length 199
  TOP w0.231: v1(126.72,201.03) 126.92,201.23 SITE1.24
  L03_SIGNAL w0.145: D120.16 58.63,43.12 62.57,43.12 67.6,48.16 67.6,61.7 72.24,66.34 72.24,98.82 117.81,144.4 117.81,163.44 119.02,164.65 120.33,164.65 121.11,165.43 121.11,175.58 123.46,177.92 123.46,180.01 123.85,180.4 123.85,180.45 127.39,183.99 127.39,199.5 126.72,200.17 v1(126.72,201.03)
D12101: length 202.3
  TOP w0.231: SITE2.156 191.92,214.03 v1(191.32,214.63)
  L03_SIGNAL w0.145: v1(191.32,214.63) 190.54,213.85 189.53,213.85 186.98,211.3 186.98,208.69 186.26,207.97 186.26,204.06 185.61,203.4 182.96,203.4 177.42,197.86 177.42,188.59 175.53,186.7 175.53,184.78 170.16,179.41 170.16,176.14 156.4,162.38 155.08,162.38 152.03,159.34 152.03,156.84 145.61,150.42 145.61,131.37 134.25,120.02 134.25,91.44 132.35,89.53 96.15,89.53 D121.01
D12102: length 203.7
  TOP w0.203: SITE2.176 193.59,206.03 190.34,202.78 178.07,202.78 175.26,199.96 175.26,190.19 172.97,187.9 161.28,187.9 156.05,193.12 153.26,193.12 v2(152.6,192.47)
  L05_SIGNAL w0.135: 94.24,101.11 94.24,109.72 107.71,123.19 123.66,123.19 124.75,124.28 124.75,162.38 124.92,162.55 124.92,179.06 126.31,180.44 151.79,180.44 153.53,182.19 153.53,192.91 153.25,193.19 152.87,193.19 152.6,192.92 v2(152.6,192.47)
  L05_SIGNAL w0.145: 94.24,101.11 93.4,100.28 92.62,100.28 91.71,99.37 D121.02
D12103: length 198.4
  TOP w0.231: SITE2.157 190.93,213.63 v1(189.92,214.63)
  L03_SIGNAL w0.145: D121.03 100.6,90.17 131.71,90.17 133.62,92.07 133.62,120.28 144.97,131.63 144.97,151.05 151.4,157.48 151.4,160.02 153.94,162.56 153.94,163.08 167.93,177.07 167.93,180.53 175.99,188.59 175.99,200.12 177.65,201.78 177.65,204.06 178.29,204.7 185.18,204.7 185.59,205.11 185.59,208.42 186.32,209.15 186.32,211.6 189.35,214.63 v1(189.92,214.63)
D12104: length 203.7
  TOP w0.203: SITE2.175 193.21,206.43 190.11,203.33 177.85,203.33 174.71,200.19 174.71,190.42 172.74,188.44 161.51,188.44 156.28,193.67 153.26,193.67 v2(152.6,194.33)
  L05_SIGNAL w0.135: v2(152.6,194.33) 152.6,193.87 152.87,193.6 153.42,193.6 153.94,193.08 153.94,182.02 151.96,180.03 126.48,180.03 125.33,178.89 125.33,162.38 125.16,162.21 125.16,124.11 123.83,122.79 107.88,122.79 94.65,109.55 94.65,101.2
  L05_SIGNAL w0.145: D121.04 94.65,101.2
D12105: length 282.8
  TOP w0.231: SITE2.152 191.92,215.63 v1(191.32,216.23)
  L03_SIGNAL w0.145: D121.05 100.64,95.21 100.64,93.05 102.88,90.8 131.45,90.8 132.98,92.34 132.98,120.54 144.34,131.9 144.34,154.23 149.49,159.38 149.49,161.93 152.14,164.57 154.26,164.57 166.2,176.51 166.2,183.54 172.12,189.47 172.12,201.42 172.49,201.78 173.54,201.78 173.79,201.53 173.79,189.45 169.47,185.14 169.47,184.31 169.68,184.1 170.35,184.1 175.36,189.11 175.36,200.38 175.8,200.83 175.8,203.03 174.69,204.14 174.69,215.35 175.3,215.96 176.21,215.96 176.63,215.54 176.63,205.39 176.92,205.09 177.79,205.09 178.02,205.33 178.02,215.5 178.46,215.94 179.56,215.94 179.86,215.64 179.86,205.67 180.2,205.33 181.28,205.33 181.61,205.65 181.61,215.35 182.3,216.04 188.34,216.04 188.96,215.42 190.51,215.42 v1(191.32,216.23)
D12106: length 203.7
  TOP w0.203: SITE2.170 188.88,208.43 188.81,208.36 169.34,208.36 165.52,204.53 160.1,204.53 156.27,208.36 153.26,208.36 v2(152.6,207.71)
  L05_SIGNAL w0.135: 104.41,101.2 104.41,113.72 110.39,119.69 129.15,119.69 131.98,122.52 131.98,173.8 133.86,175.68 152.48,175.68 156.23,179.43 156.23,185.93 157.34,187.04 157.34,199.22 154.17,202.4 154.17,208.11 153.84,208.43 152.87,208.43 152.6,208.16 v2(152.6,207.71)
  L05_SIGNAL w0.145: 104.41,101.2 103.93,100.72 103.06,100.72 101.87,99.53 D121.06
D12107: length 195.6
  TOP w0.231: v1(189.92,216.23) 190.93,215.23 SITE2.153
  L03_SIGNAL w0.145: v1(189.92,216.23) 188.93,217.22 183.93,217.22 183.53,216.82 173.23,216.82 172.38,215.98 172.38,202.96 170.48,201.06 170.48,190.54 165.48,185.53 165.48,176.92 155.49,166.93 153.23,166.93 148.86,162.56 148.86,160.02 143.7,154.86 143.7,132.16 132.35,120.8 132.35,92.6 131.19,91.44 109.49,91.44 D121.07
D12108: length 203.7
  TOP w0.203: v2(152.6,209.57) 153.26,208.91 156.49,208.91 160.32,205.08 165.29,205.08 169.11,208.9 188.81,208.9 188.88,208.83 SITE2.169
  L05_SIGNAL w0.135: v2(152.6,209.57) 152.6,209.11 152.87,208.84 154.01,208.84 154.57,208.28 154.57,202.56 157.75,199.39 157.75,186.87 156.64,185.76 156.64,179.26 152.65,175.27 134.03,175.27 132.39,173.63 132.39,122.35 129.32,119.28 110.55,119.28 104.82,113.55 104.82,101.19
  L05_SIGNAL w0.145: D121.08 104.82,101.19
D12109: length 282.8
  TOP w0.231: SITE2.149 197.72,216.83 v1(198.32,217.43)
  L03_SIGNAL w0.145: D121.09 113.93,92.07 130.93,92.07 131.71,92.86 131.71,121.07 143.07,132.42 143.07,158.04 147.76,162.73 147.76,165.32 148.2,165.76 150.65,165.76 159.61,174.72 162.31,174.72 164.76,177.17 164.76,213.54 165.15,213.93 166.2,213.93 166.55,213.57 166.55,195.15 167.04,194.67 167.04,189.99 167.57,189.45 168.34,189.45 168.7,189.82 168.7,195.15 168.21,195.65 168.21,217.75 168.57,218.12 169.38,218.12 169.74,217.76 169.74,203.56 170.15,203.15 170.93,203.15 171.11,203.33 171.11,217.16 171.7,217.75 178.67,217.75 181.23,220.32 190.91,220.32 193.11,218.12 197.63,218.12 v1(198.32,217.43)
D12110: length 203.7
  TOP w0.203: v2(163.41,207.71) 164.06,208.36 164.9,208.36 166.88,210.35 188.34,210.35 189.46,209.23 SITE2.168
  L05_SIGNAL w0.135: v2(163.41,207.71) 163.41,208.16 163.68,208.43 164.06,208.43 164.33,208.16 164.33,205.33 159.65,200.66 159.65,174.62 157.9,172.87 136.88,172.87 134.77,170.76 134.77,167.72 141.97,160.52 141.97,127.91 130.93,116.88 115.37,116.88 114.37,115.87 114.37,113.6 115.48,112.48 115.48,110.04 114.75,109.31 110.06,109.31 109.19,108.44 109.19,105.01 110.31,103.88 114.19,103.88 114.71,103.37 114.71,100.97
  L05_SIGNAL w0.145: D121.10 113.35,100.38 114.13,100.38 114.71,100.97
D12111: length 195.1
  L03_SIGNAL w0.145: D121.11 118.38,92.71 130.66,92.71 131.08,93.13 131.08,121.33 142.43,132.69 142.43,158.67 146.95,163.19 146.95,165.86 148.51,167.42 151.11,167.42 159.34,175.65 161.98,175.65 162.83,176.49 162.83,189.67 162.12,190.38 162.12,213.03 167.97,218.88 178.53,218.88 180.61,220.96 196.24,220.96 v1(198.36,218.83)
D12112: length 203.7
  TOP w0.203: v2(163.41,209.57) 164.06,208.91 164.67,208.91 166.66,210.9 188.57,210.9 189.83,209.63 SITE2.167
  L05_SIGNAL w0.135: v2(163.41,209.57) 163.41,209.11 163.68,208.84 164.23,208.84 164.74,208.33 164.74,205.16 160.06,200.49 160.06,174.46 158.06,172.46 137.05,172.46 135.18,170.59 135.18,167.89 142.38,160.69 142.38,127.74 131.1,116.47 115.54,116.47 114.77,115.7 114.77,113.77 115.89,112.65 115.89,109.87 114.92,108.9 110.23,108.9 109.6,108.27 109.6,105.17 110.48,104.29 114.36,104.29 115.12,103.54 115.12,101.05
  L05_SIGNAL w0.145: D121.12 115.12,101.05
D12113: length 203.7
  TOP w0.203: v2(167.84,192.47) 168.5,193.12 170.94,193.12 172.32,194.5 172.32,201.8 175.22,204.7 189.67,204.7 191.8,206.83 SITE2.174
  L05_SIGNAL w0.135: v2(167.84,192.47) 167.84,192.92 167.58,193.18 167.39,193.18 167.05,192.84 167.05,191.39 167.75,190.69 167.75,188.49 165.78,186.52 165.78,170.65 162.49,167.36 148.59,167.36 148,166.76 148,165.72 148.47,165.24 150.66,165.24 151.5,164.4 151.5,162.89 147.93,159.32 147.93,147.79 148.64,147.07 149.33,147.07 150.06,147.81 150.06,154.51 150.99,155.44 152.51,155.44 153.08,154.87 153.08,129.17 132.29,108.38 132.29,93.23 131,91.94 122.99,91.94 121.71,93.22 121.71,94.46
  L05_SIGNAL w0.145: D121.13 121.71,94.46
D12114: length 203.7
  TOP w0.203: v2(163.41,192.47) 164.06,193.12 164.87,193.12 165.64,193.89 165.64,199.92 172.24,206.52 189.56,206.52 190.67,207.63 SITE2.172
  L05_SIGNAL w0.135: v2(163.41,192.47) 163.41,192.92 163.68,193.19 164.1,193.19 164.38,192.91 164.38,191.65 162.83,190.1 162.83,171.98 161.1,170.25 142.46,170.25 140.69,168.48 140.69,165.76 144.91,161.55 144.91,126.03 129.69,110.81 129.69,107.72 128.89,106.93 127.34,106.93 126.87,107.39 126.87,114.23 126.36,114.74 119.65,114.74 118.6,113.69 118.6,111.68 119.52,110.76 121.95,110.76 122.6,110.11 122.6,108.81 122.09,108.3 119.31,108.3 118.6,107.59 118.6,104.41 119.67,103.34 124.31,103.34 124.82,102.83 124.82,101.06
  L05_SIGNAL w0.145: D121.14 123.52,100.39 124.15,100.39 124.82,101.06
D12115: length 203.7
  TOP w0.203: SITE2.173 191.43,207.23 189.44,205.25 175,205.25 171.77,202.02 171.77,194.73 170.71,193.67 168.5,193.67 v2(167.84,194.33)
  L05_SIGNAL w0.135: 122.12,94.5 122.12,93.39 123.16,92.35 130.83,92.35 131.88,93.4 131.88,108.55 152.67,129.34 152.67,154.7 152.34,155.03 151.16,155.03 150.47,154.34 150.47,147.64 149.5,146.67 148.47,146.67 147.52,147.62 147.52,159.49 151.09,163.06 151.09,164.23 150.49,164.84 148.3,164.84 147.59,165.55 147.59,166.93 148.42,167.77 162.32,167.77 165.37,170.81 165.37,186.69 167.34,188.66 167.34,190.52 166.64,191.22 166.64,193.01 167.23,193.6 167.57,193.6 167.84,193.87 v2(167.84,194.33)
  L05_SIGNAL w0.145: 122.12,94.5 122.6,94.99 123.46,94.99 124.73,96.26 D121.15
D12116: length 203.7
  TOP w0.203: v2(163.41,194.33) 164.06,193.67 164.64,193.67 165.09,194.12 165.09,200.15 172.01,207.07 189.33,207.07 190.3,208.03 SITE2.171
  L05_SIGNAL w0.135: v2(163.41,194.33) 163.41,193.87 163.68,193.6 164.27,193.6 164.79,193.08 164.79,191.49 163.24,189.93 163.24,171.81 161.27,169.84 142.63,169.84 141.1,168.31 141.1,165.93 145.32,161.71 145.32,125.86 130.1,110.64 130.1,107.55 129.06,106.52 127.17,106.52 126.46,107.22 126.46,114.06 126.19,114.33 119.82,114.33 119.01,113.52 119.01,111.85 119.69,111.17 122.12,111.17 123.01,110.28 123.01,108.64 122.26,107.89 119.48,107.89 119.01,107.42 119.01,104.58 119.84,103.75 124.48,103.75 125.23,103 125.23,101.1
  L05_SIGNAL w0.145: D121.16 125.23,101.1
D12201: length 168.3
  L05_SIGNAL w0.135: 91.07,74.3 91.07,68.81 96.51,63.37 140.74,63.37 154.53,77.17 154.53,83.23 168.45,97.15 195.17,97.15 201.87,103.85 201.87,129.09
  L05_SIGNAL w0.145: 91.07,74.3 D122.01 ; 201.87,129.09 202.14,129.36 v1(203.26,129.36)
D12202: length 203.7
  TOP w0.203: SITE2.2 198.12,201.37 197.55,200.8 183.61,200.8 180.49,197.69 180.49,193.65 179.97,193.12 179.3,193.12 v2(178.65,192.47)
  L05_SIGNAL w0.135: v2(178.65,192.47) 178.65,192.92 178.92,193.19 179.38,193.19 179.7,192.87 179.7,191.73 179.02,191.05 173.48,191.05 170.45,188.02 170.45,182.25 167.91,179.7 167.91,167.64 159.02,158.75 159.02,156.21 155.21,152.4 155.21,128.94 135.78,109.51 135.78,92.44 133.56,90.22 98,90.22 93.94,86.15 93.94,80.97
  L05_SIGNAL w0.145: D122.02 93.94,80.97
D12203: length 168.3
  L05_SIGNAL w0.135: 91.48,74.37 91.48,68.98 96.68,63.78 140.57,63.78 154.12,77.34 154.12,83.4 168.28,97.56 195,97.56 201.46,104.02 201.46,129.09
  L05_SIGNAL w0.145: 91.48,74.37 91.92,74.8 93.62,74.8 94.25,75.43 D122.03 ; 201.46,129.09 201.19,129.36 v1(200.06,129.36)
D12204: length 203.7
  TOP w0.203: v2(178.65,194.33) 179.3,193.67 179.74,193.67 179.94,193.87 179.94,197.91 183.38,201.35 197.33,201.35 197.72,201.74 SITE2.1
  L05_SIGNAL w0.135: v2(178.65,194.33) 178.65,193.87 178.92,193.6 179.55,193.6 180.11,193.04 180.11,191.56 179.19,190.64 173.65,190.64 170.86,187.85 170.86,182.08 168.32,179.54 168.32,167.47 159.43,158.58 159.43,156.04 155.62,152.23 155.62,128.77 136.19,109.34 136.19,92.27 133.73,89.81 98.17,89.81 94.35,85.98 94.35,81.04
  L05_SIGNAL w0.145: 94.35,81.04 96.65,78.74 D122.04
D12205: length 213.5
  TOP w0.203: v2(191.9,160.49) 191.24,161.15 191.24,164.07 194.99,167.82 194.99,174.85 205.29,185.15 205.29,191.85 203.72,193.42 SITE2.16
  L05_SIGNAL w0.135: 101.13,74.39 101.13,68.83 104.06,65.91 139.26,65.91 151.7,78.34 151.7,84.4 173.93,106.64 173.93,129.83 179.83,135.72 179.83,138.56 191.17,149.91 191.17,160.23 191.44,160.49 v2(191.9,160.49)
  L05_SIGNAL w0.145: D122.05 101.13,74.39
D12206: length 213.5
  TOP w0.203: v2(176.66,185.53) 176,186.18 176,186.76 176.73,187.49 190.05,187.49 195.28,192.72 195.28,195.87 199.72,200.3 SITE2.6
  L05_SIGNAL w0.135: v2(176.66,185.53) 176.2,185.53 175.93,185.8 175.93,186.73 175.42,187.24 173.93,187.24 173.14,186.45 173.14,184.72 173.9,183.95 182.22,183.95 182.73,183.45 182.73,181.71 181.96,180.94 174.28,180.94 171.08,177.74 171.08,166.95 161.15,157.01 161.15,152.57 157.98,149.39 157.98,128.01 138.52,108.56 138.52,89.7 136.68,87.86 105.38,87.86 103.73,86.21 103.73,80.6
  L05_SIGNAL w0.145: D122.06 103.73,80.6
D12207: length 213.5
  TOP w0.203: SITE2.15 203.32,193.04 204.74,191.62 204.74,185.37 194.44,175.08 194.44,168.05 190.69,164.3 190.69,161.15 v2(190.04,160.49)
  L05_SIGNAL w0.135: v2(190.04,160.49) 190.49,160.49 190.76,160.23 190.76,150.08 179.42,138.73 179.42,135.89 173.52,130 173.52,106.81 151.29,84.57 151.29,78.51 139.09,66.32 104.23,66.32 101.54,69 101.54,74.42
  L05_SIGNAL w0.145: 101.54,74.42 102.23,75.11 103.9,75.11 104.41,75.62 D122.07
D12208: length 213.5
  TOP w0.203: v2(174.8,185.53) 175.45,186.18 175.45,186.99 176.5,188.04 189.82,188.04 194.73,192.95 194.73,196.09 199.32,200.68 SITE2.5
  L05_SIGNAL w0.135: v2(174.8,185.53) 175.25,185.53 175.52,185.8 175.52,186.56 175.25,186.84 174.1,186.84 173.55,186.28 173.55,184.89 174.07,184.36 182.39,184.36 183.14,183.62 183.14,181.54 182.13,180.53 174.45,180.53 171.49,177.57 171.49,166.78 161.56,156.84 161.56,152.4 158.38,149.22 158.38,127.84 138.93,108.39 138.93,89.53 136.85,87.45 105.55,87.45 104.14,86.04 104.14,80.73
  L05_SIGNAL w0.145: 104.14,80.73 104.5,80.37 106.03,80.37 106.95,79.46 D122.08
D12209: length 213.5
  TOP w0.203: SITE2.14 202.92,186.63 191.24,174.95 191.24,171.96 v2(191.9,171.3)
  L05_SIGNAL w0.135: v2(191.9,171.3) 191.44,171.3 191.17,171.03 191.17,168.84 191.66,168.34 194.42,168.34 196.14,166.63 196.14,162.86 195.4,162.12 193.35,162.12 190.84,164.63 187.56,164.63 186.21,163.28 186.21,149.31 177.32,140.42 177.32,137.86 171.12,131.66 171.12,108.64 170.03,107.55 163.49,107.55 148.69,92.75 148.69,80.18 136.99,68.48 113.28,68.48 111.24,70.51 111.24,74.45
  L05_SIGNAL w0.145: D122.09 111.24,74.45
D12210: length 213.5
  TOP w0.203: v2(176.66,174.72) 176,175.37 176,178.38 182.13,184.51 189.83,184.51 197.15,191.83 197.15,194.75 200.52,198.12 SITE2.8
  L05_SIGNAL w0.135: v2(176.66,174.72) 176.2,174.72 175.93,174.99 175.93,175.54 175.42,176.05 174.64,176.05 172.99,174.4 172.99,163.14 163.69,153.84 163.69,151.42 161.55,149.28 161.55,147.75 162.2,147.1 167.21,147.1 167.76,146.56 167.76,143.61 166.81,142.65 161.37,142.65 159.88,141.16 159.88,126.35 141.08,107.55 141.08,103.34 141.75,102.68 143.25,102.68 148.07,107.49 149.45,107.49 150.15,106.8 150.15,105.65 141.08,96.58 141.08,87.66 138.86,85.44 115.13,85.44 113.93,84.23 113.93,80.64
  L05_SIGNAL w0.145: D122.10 113.93,80.64
D12211: length 213.5
  TOP w0.203: v2(190.04,171.3) 190.69,171.96 190.69,175.18 202.52,187 SITE2.13
  L05_SIGNAL w0.135: v2(190.04,171.3) 190.49,171.3 190.76,171.03 190.76,168.67 191.5,167.93 194.25,167.93 195.73,166.46 195.73,163.03 195.23,162.53 193.52,162.53 191.01,165.04 187.39,165.04 185.8,163.45 185.8,149.48 176.91,140.59 176.91,138.03 170.71,131.83 170.71,108.81 169.86,107.96 163.32,107.96 148.29,92.92 148.29,80.35 136.82,68.88 113.45,68.88 111.65,70.68 111.65,74.34
  L05_SIGNAL w0.145: D122.11 114.57,75.87 113.69,74.99 112.3,74.99 111.65,74.34
D12212: length 213.5
  TOP w0.203: v2(174.8,174.72) 175.45,175.37 175.45,178.61 181.9,185.05 189.6,185.05 196.6,192.05 196.6,194.98 200.12,198.5 SITE2.7
  L05_SIGNAL w0.135: v2(174.8,174.72) 175.25,174.72 175.52,174.99 175.52,175.37 175.25,175.64 174.81,175.64 173.4,174.23 173.4,162.97 164.1,153.67 164.1,151.25 161.96,149.11 161.96,147.92 162.37,147.51 167.38,147.51 168.17,146.73 168.17,143.44 166.98,142.25 161.54,142.25 160.29,140.99 160.29,126.18 141.49,107.38 141.49,103.51 141.92,103.08 143.08,103.08 147.9,107.9 149.62,107.9 150.56,106.96 150.56,105.48 141.49,96.42 141.49,87.49 139.03,85.03 115.3,85.03 114.33,84.06 114.33,80.77
  L05_SIGNAL w0.145: D122.12 117.11,79.58 116.5,80.19 114.91,80.19 114.33,80.77
D12213: length 213.5
  TOP w0.203: v2(176.66,171.3) 176,171.96 176,172.53 176.41,172.94 178.35,172.94 187.09,181.68 190.18,181.68 198.86,190.36 198.86,193.76 201.32,196.22 SITE2.10
  L05_SIGNAL w0.135: 121.46,74.39 121.46,72.12 122.76,70.82 136.01,70.82 146.35,81.15 146.35,94.49 165.37,113.51 165.37,135.41 166.18,136.22 170.63,136.22 174.28,139.86 174.28,142.67 183.5,151.89 183.5,174.02 182.55,174.98 180.62,174.98 179.68,174.04 179.68,166.05 179.16,165.53 176.54,165.53 175.93,166.14 175.93,171.03 176.2,171.3 v2(176.66,171.3)
  L05_SIGNAL w0.145: D122.13 121.46,74.39
D12214: length 213.5
  TOP w0.203: SITE2.12 202.12,194 200.89,192.77 200.89,188.73 176,163.84 176,161.15 v2(176.66,160.49)
  L05_SIGNAL w0.135: v2(176.66,160.49) 176.2,160.49 175.93,160.76 175.93,161.31 175.42,161.82 174.32,161.82 173.48,160.98 173.48,158.42 167.51,152.45 167.51,150.65 168.66,149.49 170.32,149.49 178.61,157.78 179.84,157.78 180.73,156.89 180.73,154.74 171.26,145.27 171.26,142.28 168.87,139.88 164.52,139.88 162.83,138.2 162.83,114.56 143.6,95.33 143.6,83.11 136.34,75.85 133.68,75.85 132.88,76.65 132.88,81.88 131.66,83.1 124.75,83.1 124.12,82.46 124.12,80.67
  L05_SIGNAL w0.145: D122.14 124.12,80.67
D12215: length 213.5
  TOP w0.203: v2(174.8,171.3) 175.45,171.96 175.45,172.76 176.18,173.49 178.12,173.49 186.86,182.23 189.95,182.23 198.31,190.59 198.31,193.99 200.92,196.6 SITE2.9
  L05_SIGNAL w0.135: v2(174.8,171.3) 175.25,171.3 175.52,171.03 175.52,165.97 176.37,165.12 179.33,165.12 180.09,165.88 180.09,173.87 180.78,174.57 182.38,174.57 183.09,173.85 183.09,152.06 173.87,142.84 173.87,140.03 170.46,136.62 166.01,136.62 164.96,135.58 164.96,113.68 145.94,94.66 145.94,81.32 135.85,71.23 122.93,71.23 121.87,72.29 121.87,74.43
  L05_SIGNAL w0.145: 121.87,74.43 122.5,75.06 123.97,75.06 124.73,75.83 D122.15
D12216: length 213.5
  TOP w0.203: v2(174.8,160.49) 175.45,161.15 175.45,164.07 200.34,188.96 200.34,193 201.72,194.38 SITE2.11
  L05_SIGNAL w0.135: 124.53,80.69 124.53,82.29 124.92,82.69 131.49,82.69 132.47,81.71 132.47,76.48 133.51,75.44 136.51,75.44 144.01,82.95 144.01,95.17 163.24,114.39 163.24,138.03 164.69,139.48 169.04,139.48 171.67,142.11 171.67,145.1 181.14,154.57 181.14,157.06 180.01,158.19 178.44,158.19 170.15,149.9 168.83,149.9 167.92,150.82 167.92,152.28 173.89,158.25 173.89,160.81 174.49,161.41 175.25,161.41 175.52,161.14 175.52,160.76 175.25,160.49 v2(174.8,160.49)
  L05_SIGNAL w0.145: D122.16 127.27,79.58 126.65,80.21 125.02,80.21 124.53,80.69
